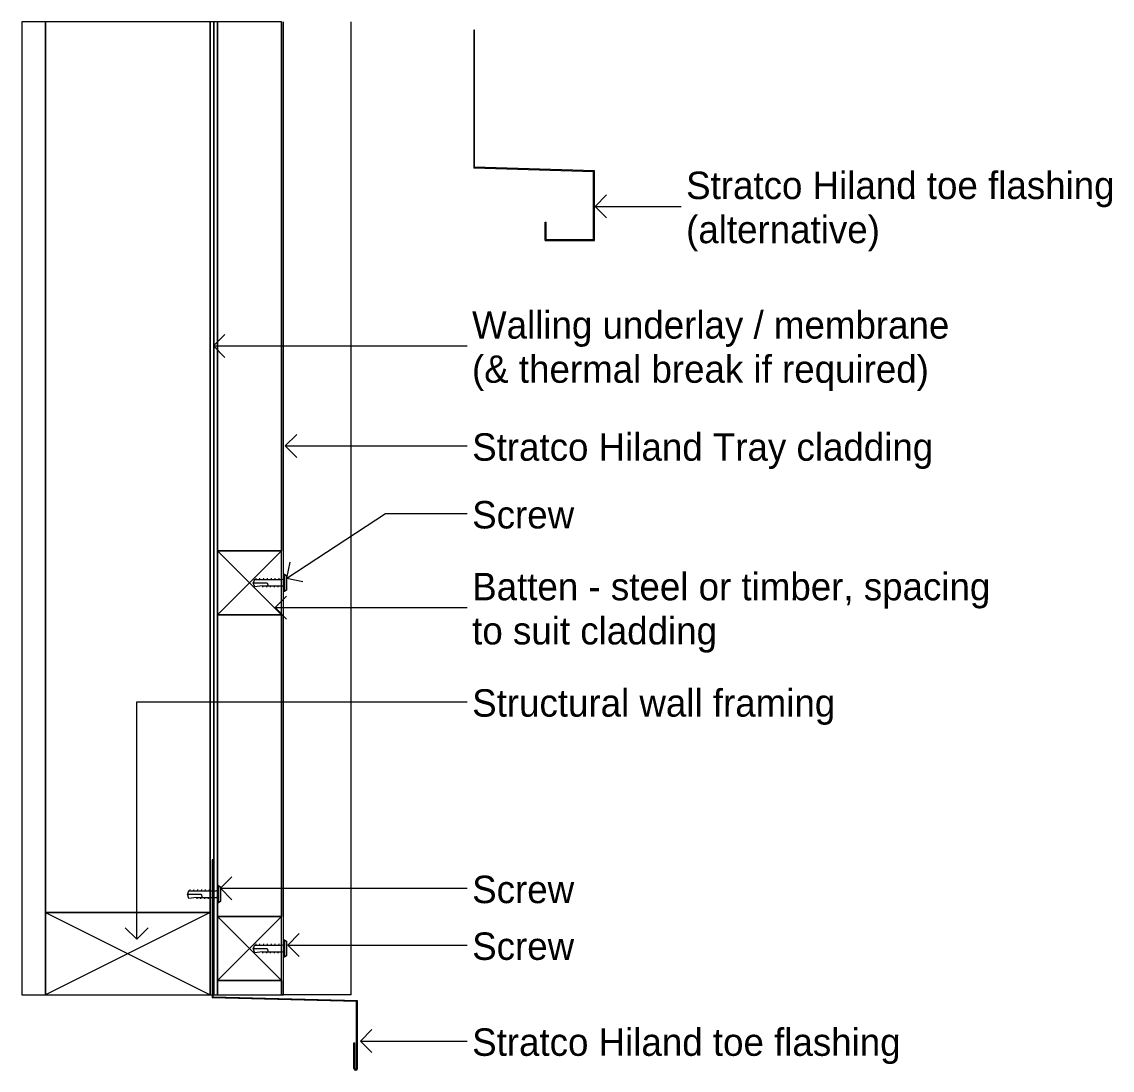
# Model space of a CAD drawing. Extents: x -2.36 to 6.66, y -3.72 to 4.13.
# Drawn here: x 0.378 to 0.974, y -0.041 to 0.532 of the extents above; entities that cross this region are included whole.
import ezdxf

# ---------------------------------------------------------------- set-up
doc = ezdxf.new("R2010")
doc.units = 0
for name, color, linetype in [('A-____-____-IDEN', 7, 'Continuous'), ('A-DETL-____-MEDM', 7, 'Continuous'), ('A-DETL-GENF-OTLN', 7, 'Continuous'), ('A-WALL-____-MCUT', 7, 'Continuous'), ('A-WALL-____-PATT', 7, 'Continuous'), ('A-WALL-FNSH-MCUT', 7, 'Continuous')]:
    doc.layers.add(name, color=color, linetype=linetype)

# ---------------------------------------------------------------- blocks, each defined once
blk = doc.blocks.new('Detail_Stratco_Cladding Side Profile - 38mm-Hiland Nailstrip Toe')
at = {"layer": 'A-DETL-____-MEDM'}
for p, q in [((-2, 0.53208), (-2, 0.24282)), ((-1.999, 0), (-1.999, 0.53208)), ((-2, 0.20782), (-2, 0.04282)), ((-2, 0.00782), (-2, 0)), ((-2, 0), (-1.999, 0))]:
    blk.add_line(p, q, dxfattribs=at)
at = {"layer": 'A-DETL-GENF-OTLN'}
for q in [(-1.962, 0.53208), (-2, 0)]:
    blk.add_line((-1.962, 0), q, dxfattribs=at)
blk = doc.blocks.new('Detail_Stratco_Hiland_Tray_Toe - Rib Height 38mm-Hiland Nailstrip Toe')
at = {"layer": 'A-DETL-GENF-OTLN'}
for p, q in [((-2.0375, 0.07375), (-2.038, 0.07375)), ((-2.038, 0.07375), (-2.038, -0.00174)), ((-2.0375, -0.00125), (-2.0375, 0.07375)), ((-1.959, -0.00374), (-2.038, -0.00174)), ((-1.9585, -0.00325), (-2.0375, -0.00125)), ((-1.959, -0.04025), (-1.959, -0.00374)), ((-1.9585, -0.04025), (-1.9585, -0.00325)), ((-1.9605, -0.04025), (-1.9605, -0.02625)), ((-1.9605, -0.02625), (-1.96, -0.02625)), ((-1.96, -0.04025), (-1.96, -0.02625))]:
    blk.add_line(p, q, dxfattribs=at)
for radius in [0.001, 0.0005]:
    blk.add_arc((-1.9595, -0.04025), radius, 180, 0, dxfattribs=at)
blk = doc.blocks.new('DET_Screw Metal Wafer - DET_Screw Metal Wafer-Hiland Nailstrip Toe')
at = {"layer": 'A-DETL-GENF-OTLN'}
for p, q in [((-2.05088, 0.05675), (-2.05151, 0.055)), ((-2.05151, 0.055), (-2.0439, 0.055)), ((-2.05067, 0.05268), (-2.05151, 0.055)), ((-2.05088, 0.05675), (-2.0358, 0.05675)), ((-2.05018, 0.05675), (-2.04994, 0.0575)), ((-2.04808, 0.05675), (-2.04784, 0.0575)), ((-2.04598, 0.05675), (-2.04574, 0.0575)), ((-2.0439, 0.055), (-2.0434, 0.05325)), ((-2.04388, 0.05675), (-2.04364, 0.0575)), ((-2.04178, 0.05675), (-2.04154, 0.0575)), ((-2.03968, 0.05675), (-2.03945, 0.0575)), ((-2.03759, 0.05675), (-2.03735, 0.0575)), ((-2.035, 0.0591), (-2.035, 0.0509)), ((-2.03429, 0.05955), (-2.03336, 0.05901)), ((-2.03429, 0.05045), (-2.03429, 0.05955)), ((-2.03336, 0.05901), (-2.03336, 0.05099)), ((-2.0466, 0.05325), (-2.05067, 0.05268)), ((-2.0466, 0.05325), (-2.0358, 0.05325)), ((-2.04625, 0.0525), (-2.04602, 0.05325)), ((-2.04415, 0.0525), (-2.04392, 0.05325)), ((-2.04206, 0.0525), (-2.04182, 0.05325)), ((-2.03996, 0.0525), (-2.03972, 0.05325)), ((-2.03786, 0.0525), (-2.03762, 0.05325)), ((-2.03336, 0.05099), (-2.0343, 0.05044))]:
    blk.add_line(p, q, dxfattribs=at)
for centre, radius, start, end in [((-2.0345, 0.0591), 0.0005, 66.33018, 180), ((-2.0358, 0.05755), 0.0008, 270, 360), ((-2.0358, 0.05245), 0.0008, 360, 90), ((-2.0345, 0.0509), 0.0005, 180, 293.66982)]:
    blk.add_arc(centre, radius, start, end, dxfattribs=at)
blk = doc.blocks.new('Detail_Stratco_Hiland_Tray_Toe 1 - Rib Height 38mm-Hiland Nailstrip Toe')
at = {"layer": 'A-DETL-GENF-OTLN'}
for p, q in [((-1.8945, 0.5275), (-1.895, 0.5275)), ((-1.895, 0.5275), (-1.895, 0.45202)), ((-1.8945, 0.4525), (-1.8945, 0.5275)), ((-1.8295, 0.45002), (-1.895, 0.45202)), ((-1.829, 0.4505), (-1.8945, 0.4525)), ((-1.8295, 0.413), (-1.8295, 0.45002)), ((-1.829, 0.4125), (-1.829, 0.4505)), ((-1.856, 0.4125), (-1.856, 0.4225)), ((-1.856, 0.4225), (-1.8555, 0.4225)), ((-1.8555, 0.413), (-1.8555, 0.4225)), ((-1.856, 0.4125), (-1.829, 0.4125)), ((-1.8555, 0.413), (-1.8295, 0.413))]:
    blk.add_line(p, q, dxfattribs=at)
blk = doc.blocks.new('DET_ST_Framing Detail Timber - 35x35 Batten-Hiland Nailstrip Toe')
at = {"layer": 'A-DETL-____-MEDM'}
for p, q in [((-2, 0.04282), (-2.035, 0.04282)), ((-2.035, 0.04282), (-2.035, 0.00782)), ((-2, 0.00782), (-2, 0.04282)), ((-2.035, 0.00782), (-2, 0.00782))]:
    blk.add_line(p, q, dxfattribs=at)
at = {"layer": 'A-DETL-GENF-OTLN'}
for p, q in [((-2.035, 0.04282), (-2, 0.00782)), ((-2, 0.04282), (-2.035, 0.00782))]:
    blk.add_line(p, q, dxfattribs=at)
blk = doc.blocks.new('DET_ST_Framing Detail Timber - 45x90-Hiland Nailstrip Toe')
at = {"layer": 'A-DETL-____-MEDM'}
for p, q in [((-2.039, 0.045), (-2.129, 0.045)), ((-2.129, 0.045), (-2.129, 0)), ((-2.039, 0), (-2.039, 0.045)), ((-2.129, 0), (-2.039, 0))]:
    blk.add_line(p, q, dxfattribs=at)
at = {"layer": 'A-DETL-GENF-OTLN'}
for p, q in [((-2.129, 0.045), (-2.039, 0)), ((-2.039, 0.045), (-2.129, 0))]:
    blk.add_line(p, q, dxfattribs=at)

msp = doc.modelspace()

# ---------------------------------------------------------------- linework, layer by layer
at = {"layer": 'A-____-____-IDEN'}
for p, q in [((0.69124, 0.43116), (0.69749, 0.43741)), ((0.69124, 0.43116), (0.69749, 0.42491)), ((0.69124, 0.43116), (0.70316, 0.43116)), ((0.70316, 0.43116), (0.73825, 0.43116)), ((0.4826, 0.35483), (0.48885, 0.36108)), ((0.4826, 0.35483), (0.48885, 0.34858)), ((0.4826, 0.35483), (0.50012, 0.35483)), ((0.50012, 0.35483), (0.62132, 0.35483)), ((0.52187, 0.30015), (0.52812, 0.3064)), ((0.52187, 0.30015), (0.52812, 0.2939)), ((0.52187, 0.30015), (0.53755, 0.30015)), ((0.53755, 0.30015), (0.62132, 0.30015)), ((0.52275, 0.22785), (0.57673, 0.2631)), ((0.57673, 0.2631), (0.62132, 0.2631)), ((0.52275, 0.22785), (0.52456, 0.2365)), ((0.52275, 0.22785), (0.5314, 0.22603)), ((0.51627, 0.21174), (0.52252, 0.21799)), ((0.51627, 0.21174), (0.52252, 0.20549)), ((0.51627, 0.21174), (0.53348, 0.21174)), ((0.53348, 0.21174), (0.62132, 0.21174)), ((0.44068, 0.16018), (0.62132, 0.16018)), ((0.44068, 0.03044), (0.44068, 0.16018)), ((0.48649, 0.05821), (0.49274, 0.06446)), ((0.48649, 0.05821), (0.49274, 0.05196)), ((0.48649, 0.05821), (0.54781, 0.05821)), ((0.54781, 0.05821), (0.62132, 0.05821)), ((0.44068, 0.03044), (0.43443, 0.03669)), ((0.44068, 0.03044), (0.44693, 0.03669)), ((0.52321, 0.02717), (0.52946, 0.03342)), ((0.52321, 0.02717), (0.52946, 0.02092)), ((0.52321, 0.02717), (0.53348, 0.02717)), ((0.53348, 0.02717), (0.62132, 0.02717)), ((0.56296, -0.02529), (0.56921, -0.01904)), ((0.56296, -0.02529), (0.56921, -0.03154)), ((0.56296, -0.02529), (0.57673, -0.02529)), ((0.57673, -0.02529), (0.62132, -0.02529))]:
    msp.add_line(p, q, dxfattribs=at)
at = {"layer": 'A-WALL-____-MCUT'}
for p, q in [((0.39089, 0.53208), (0.39089, 0.045)), ((0.48089, 0.53208), (0.48089, 0.045)), ((0.48289, 0.53208), (0.48289, 0)), ((0.48489, 0.53208), (0.48489, 0.24282)), ((0.48489, 0.20782), (0.48489, 0.04282)), ((0.48489, 0.00782), (0.48489, 0)), ((0.48089, 0), (0.51989, 0))]:
    msp.add_line(p, q, dxfattribs=at)
at = {"layer": 'A-WALL-____-PATT'}
for p, q in [((0.39089, 0.53208), (0.37789, 0.53208)), ((0.37789, 0.53208), (0.37789, 0)), ((0.39089, 0), (0.39089, 0.53208)), ((0.48089, 0.53208), (0.39089, 0.53208)), ((0.39089, 0.53208), (0.39089, 0.045)), ((0.48089, 0.045), (0.48089, 0.53208)), ((0.48289, 0.53208), (0.48089, 0.53208)), ((0.48089, 0.53208), (0.48089, 0)), ((0.48289, 0), (0.48289, 0.53208)), ((0.48489, 0.53208), (0.48289, 0.53208)), ((0.48289, 0.53208), (0.48289, 0.00782)), ((0.48489, 0), (0.48489, 0.53208)), ((0.51989, 0.53208), (0.48489, 0.53208)), ((0.48489, 0.53208), (0.48489, 0.24282)), ((0.51989, 0.24282), (0.51989, 0.53208)), ((0.48489, 0.24282), (0.51989, 0.24282)), ((0.51989, 0.20782), (0.48489, 0.20782)), ((0.48489, 0.20782), (0.48489, 0.04282)), ((0.51989, 0.04282), (0.51989, 0.20782)), ((0.39089, 0.045), (0.48089, 0.045)), ((0.48489, 0.04282), (0.51989, 0.04282)), ((0.48289, 0.00782), (0.48289, 0)), ((0.51989, 0.00782), (0.48489, 0.00782)), ((0.48489, 0.00782), (0.48489, 0)), ((0.51989, 0), (0.51989, 0.00782)), ((0.37789, 0), (0.39089, 0)), ((0.48089, 0), (0.48289, 0)), ((0.48289, 0), (0.48489, 0)), ((0.48489, 0), (0.51989, 0))]:
    msp.add_line(p, q, dxfattribs=at)
at = {"layer": 'A-WALL-FNSH-MCUT'}
for p, q in [((0.37789, 0.53208), (0.37789, 0)), ((0.37789, 0), (0.39089, 0))]:
    msp.add_line(p, q, dxfattribs=at)

# ---------------------------------------------------------------- block references
at = {"layer": 'A-DETL-GENF-OTLN'}
for name, p in [('Detail_Stratco_Cladding Side Profile - 38mm-Hiland Nailstrip Toe', (2.51989, 0)), ('Detail_Stratco_Hiland_Tray_Toe 1 - Rib Height 38mm-Hiland Nailstrip Toe', (2.51989, 0)), ('DET_ST_Framing Detail Timber - 35x35 Batten-Hiland Nailstrip Toe', (2.51989, 0.2)), ('DET_Screw Metal Wafer - DET_Screw Metal Wafer-Hiland Nailstrip Toe', (2.55589, 0.17032)), ('Detail_Stratco_Hiland_Tray_Toe - Rib Height 38mm-Hiland Nailstrip Toe', (2.51989, 0)), ('DET_Screw Metal Wafer - DET_Screw Metal Wafer-Hiland Nailstrip Toe', (2.51989, 0)), ('DET_ST_Framing Detail Timber - 45x90-Hiland Nailstrip Toe', (2.51989, 0)), ('DET_ST_Framing Detail Timber - 35x35 Batten-Hiland Nailstrip Toe', (2.51989, 0)), ('DET_Screw Metal Wafer - DET_Screw Metal Wafer-Hiland Nailstrip Toe', (2.55589, -0.02968))]:
    msp.add_blockref(name, p, dxfattribs=at)

# ---------------------------------------------------------------- texts
at = {"layer": 'A-____-____-IDEN'}
for s, p in [('Stratco Hiland toe flashing', (0.74096, 0.43514)), ('(alternative)', (0.74096, 0.411)), ('Walling underlay / membrane', (0.62393, 0.35881)), ('(& thermal break if required)', (0.62393, 0.33467)), ('Stratco Hiland Tray cladding', (0.62403, 0.29205)), ('Screw', (0.62403, 0.255)), ('Batten - steel or timber, spacing', (0.62403, 0.21572)), ('to suit cladding', (0.62403, 0.19158)), ('Structural wall framing', (0.62403, 0.15208)), ('Screw', (0.62403, 0.05011)), ('Screw', (0.62403, 0.01907)), ('Stratco Hiland toe flashing', (0.62403, -0.03339))]:
    msp.add_text(s, height=0.015, dxfattribs=at).set_placement(p)

doc.saveas('drawing.dxf')
